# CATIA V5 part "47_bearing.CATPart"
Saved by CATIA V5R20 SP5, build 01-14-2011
Part number: 47_bearing
Bounding box of the stored display mesh (mm): x -14.994 to 14.994, y 125.368 to 155.356, z -151.5 to -143.5
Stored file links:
  C:\Documents and Settings\anizard\Bureau\13\47_bearing.CATPart
  C:\Documents and Settings\anizard\Bureau\13\anizard.CATProduct
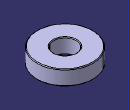
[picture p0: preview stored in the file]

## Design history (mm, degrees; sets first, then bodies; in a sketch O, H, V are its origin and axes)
Set1
  Plane1: linked copy from another document
  Plane2: linked copy from another document
  Point1: linked copy from another document
  Line1: linked copy from another document
  Point2: linked copy from another document
  Plane3: linked copy from another document
Body1 (main body)
  Sketch1 on Plane1, origin (0, 0, 0), H (0, 1, 0), V (0, 0, 1)
    line L1 (146.7155, -143.5) -> (155.0084, -143.5)
    line L2 (155.3619, -143.8536) -> (155.3619, -151.1464)
    line L3 (155.0084, -151.5) -> (146.7155, -151.5)
    line L4 (146.3619, -151.1464) -> (146.3619, -143.8536)
    line L5 (155.3619, -151.1464) -> (155.0084, -151.5)
    line L6 (155.0084, -143.5) -> (155.3619, -143.8536)
    line L7 (146.7155, -151.5) -> (146.3619, -151.1464)
    line L8 (146.7155, -143.5) -> (146.3619, -143.8536)
    reference intersected line E1 through (0, -151.5) direction (-1, 0) from Plane2
    reference projected point E2 (146.3619, -122.5) from Point2
    reference intersected line E3 through (0, -143.5) direction (-1, 0) from Plane3
    reference projected point E4 (155.3619, -122.5) from Point1
    angle L2 L5 = 45
    length L5 = 0.5
    angle L1 L6 = 45
    length L6 = 0.5
    angle L3 L7 = 45
    length L7 = 0.5
    angle L1 L8 = 45
    length L8 = 0.5
    horizontal: L1 H, L3 H
    vertical: L2 V, L4 V
    coincidence: L3 E1, L4 E2, L1 E3, L2 E4
  Shaft1: profile Sketch1, axis Line1, angle 360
